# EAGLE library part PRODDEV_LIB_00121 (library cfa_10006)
ATmega2561-16AU, IC AVR MCU 256K 16MHZ 64TQFP 256 Kbytes FLASH 8 Kbytes SRAM 4 Kbytes EEPROM DUAL USART 8-channel 10 bit ADC
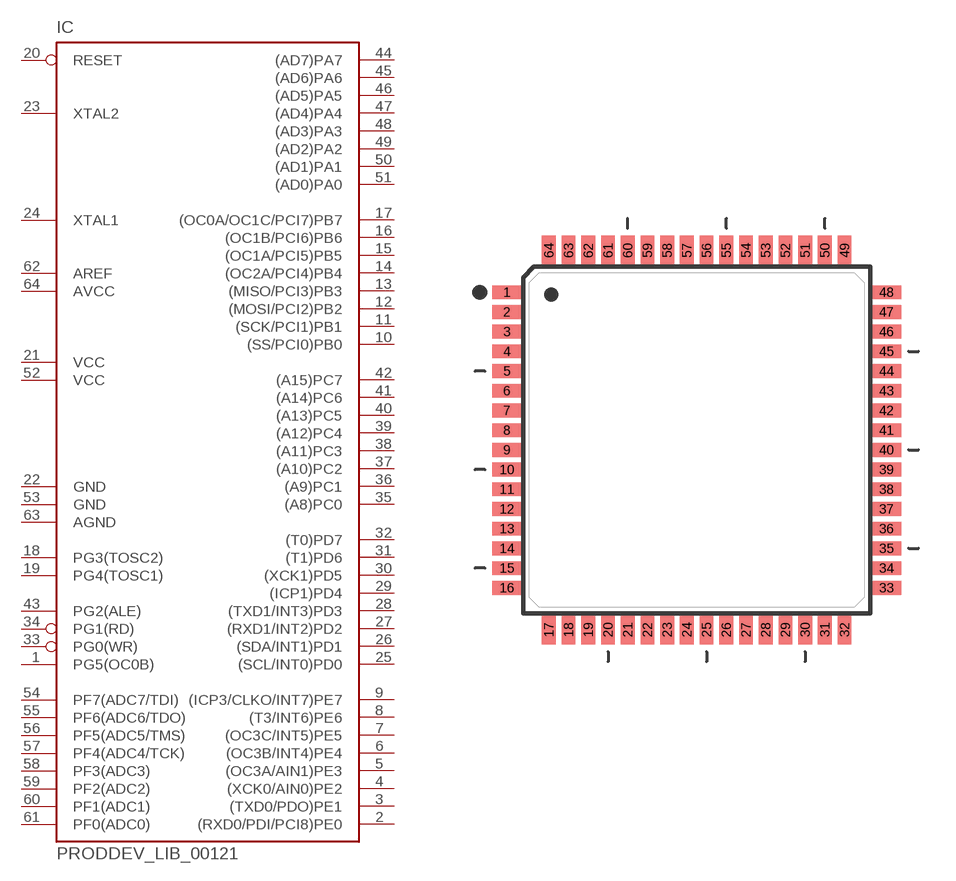
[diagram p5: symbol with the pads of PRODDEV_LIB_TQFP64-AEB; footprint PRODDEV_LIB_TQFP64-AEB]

Designator prefix IC

## PRODDEV_LIB_00121  [PRODDEV_LIB_TQFP64-AEB]
1  PG5(OC0B)
2  (RXD0/PDI/PCI8)PE0
3  (TXD0/PDO)PE1
4  (XCK0/AIN0)PE2
5  (OC3A/AIN1)PE3
6  (OC3B/INT4)PE4
7  (OC3C/INT5)PE5
8  (T3/INT6)PE6
9  (ICP3/CLKO/INT7)PE7
10  (SS/PCI0)PB0
11  (SCK/PCI1)PB1
12  (MOSI/PCI2)PB2
13  (MISO/PCI3)PB3
14  (OC2A/PCI4)PB4
15  (OC1A/PCI5)PB5
16  (OC1B/PCI6)PB6
17  (OC0A/OC1C/PCI7)PB7
18  PG3(TOSC2)
19  PG4(TOSC1)
20  RESET  in
21  VCC  pwr
22  GND  pwr
23  XTAL2
24  XTAL1
25  (SCL/INT0)PD0
26  (SDA/INT1)PD1
27  (RXD1/INT2)PD2
28  (TXD1/INT3)PD3
29  (ICP1)PD4
30  (XCK1)PD5
31  (T1)PD6
32  (T0)PD7
33  PG0(WR)
34  PG1(RD)
35  (A8)PC0
36  (A9)PC1
37  (A10)PC2
38  (A11)PC3
39  (A12)PC4
40  (A13)PC5
41  (A14)PC6
42  (A15)PC7
43  PG2(ALE)
44  (AD7)PA7
45  (AD6)PA6
46  (AD5)PA5
47  (AD4)PA4
48  (AD3)PA3
49  (AD2)PA2
50  (AD1)PA1
51  (AD0)PA0
52  VCC  pwr
53  GND  pwr
54  PF7(ADC7/TDI)  in
55  PF6(ADC6/TDO)  in
56  PF5(ADC5/TMS)  in
57  PF4(ADC4/TCK)  in
58  PF3(ADC3)  in
59  PF2(ADC2)  in
60  PF1(ADC1)  in
61  PF0(ADC0)  in
62  AREF  pwr
63  AGND  pwr
64  AVCC  pwr

## Footprint PRODDEV_LIB_TQFP64-AEB (pad centres in mm)
Thin Plasic Quad Flat Package JDEC Reference MS-026, Variation AEB
smd 1.194 x 0.559: 1 -7.7,6; 2 -7.7,5.2; 3 -7.7,4.4; 4 -7.7,3.6; 5 -7.7,2.8; 6 -7.7,2; 7 -7.7,1.2; 8 -7.7,0.4; 9 -7.7,-0.4; 10 -7.7,-1.2; 11 -7.7,-2; 12 -7.7,-2.8; 13 -7.7,-3.6; 14 -7.7,-4.4; 15 -7.7,-5.2; 16 -7.7,-6; 33 7.7,-6; 34 7.7,-5.2; 35 7.7,-4.4; 36 7.7,-3.6; 37 7.7,-2.8; 38 7.7,-2; 39 7.7,-1.2; 40 7.7,-0.4; 41 7.7,0.4; 42 7.7,1.2; 43 7.7,2; 44 7.7,2.8; 45 7.7,3.6; 46 7.7,4.4; 47 7.7,5.2; 48 7.7,6
smd 0.559 x 1.194: 17 -6,-7.7; 18 -5.2,-7.7; 19 -4.4,-7.7; 20 -3.6,-7.7; 21 -2.8,-7.7; 22 -2,-7.7; 23 -1.2,-7.7; 24 -0.4,-7.7; 25 0.4,-7.7; 26 1.2,-7.7; 27 2,-7.7; 28 2.8,-7.7; 29 3.6,-7.7; 30 4.4,-7.7; 31 5.2,-7.7; 32 6,-7.7; 49 6,7.7; 50 5.2,7.7; 51 4.4,7.7; 52 3.6,7.7; 53 2.8,7.7; 54 2,7.7; 55 1.2,7.7; 56 0.4,7.7; 57 -0.4,7.7; 58 -1.2,7.7; 59 -2,7.7; 60 -2.8,7.7; 61 -3.6,7.7; 62 -4.4,7.7; 63 -5.2,7.7; 64 -6,7.7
